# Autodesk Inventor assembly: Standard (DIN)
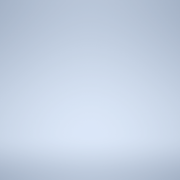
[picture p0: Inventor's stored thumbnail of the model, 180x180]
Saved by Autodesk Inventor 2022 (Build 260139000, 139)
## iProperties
Created: 2021-02
Part Number: Standard (DIN)
Document SubType Name: Assembly
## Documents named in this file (1)
- C:\Users\ENU\Desktop\New folder for ita\Standard (DIN).iam
